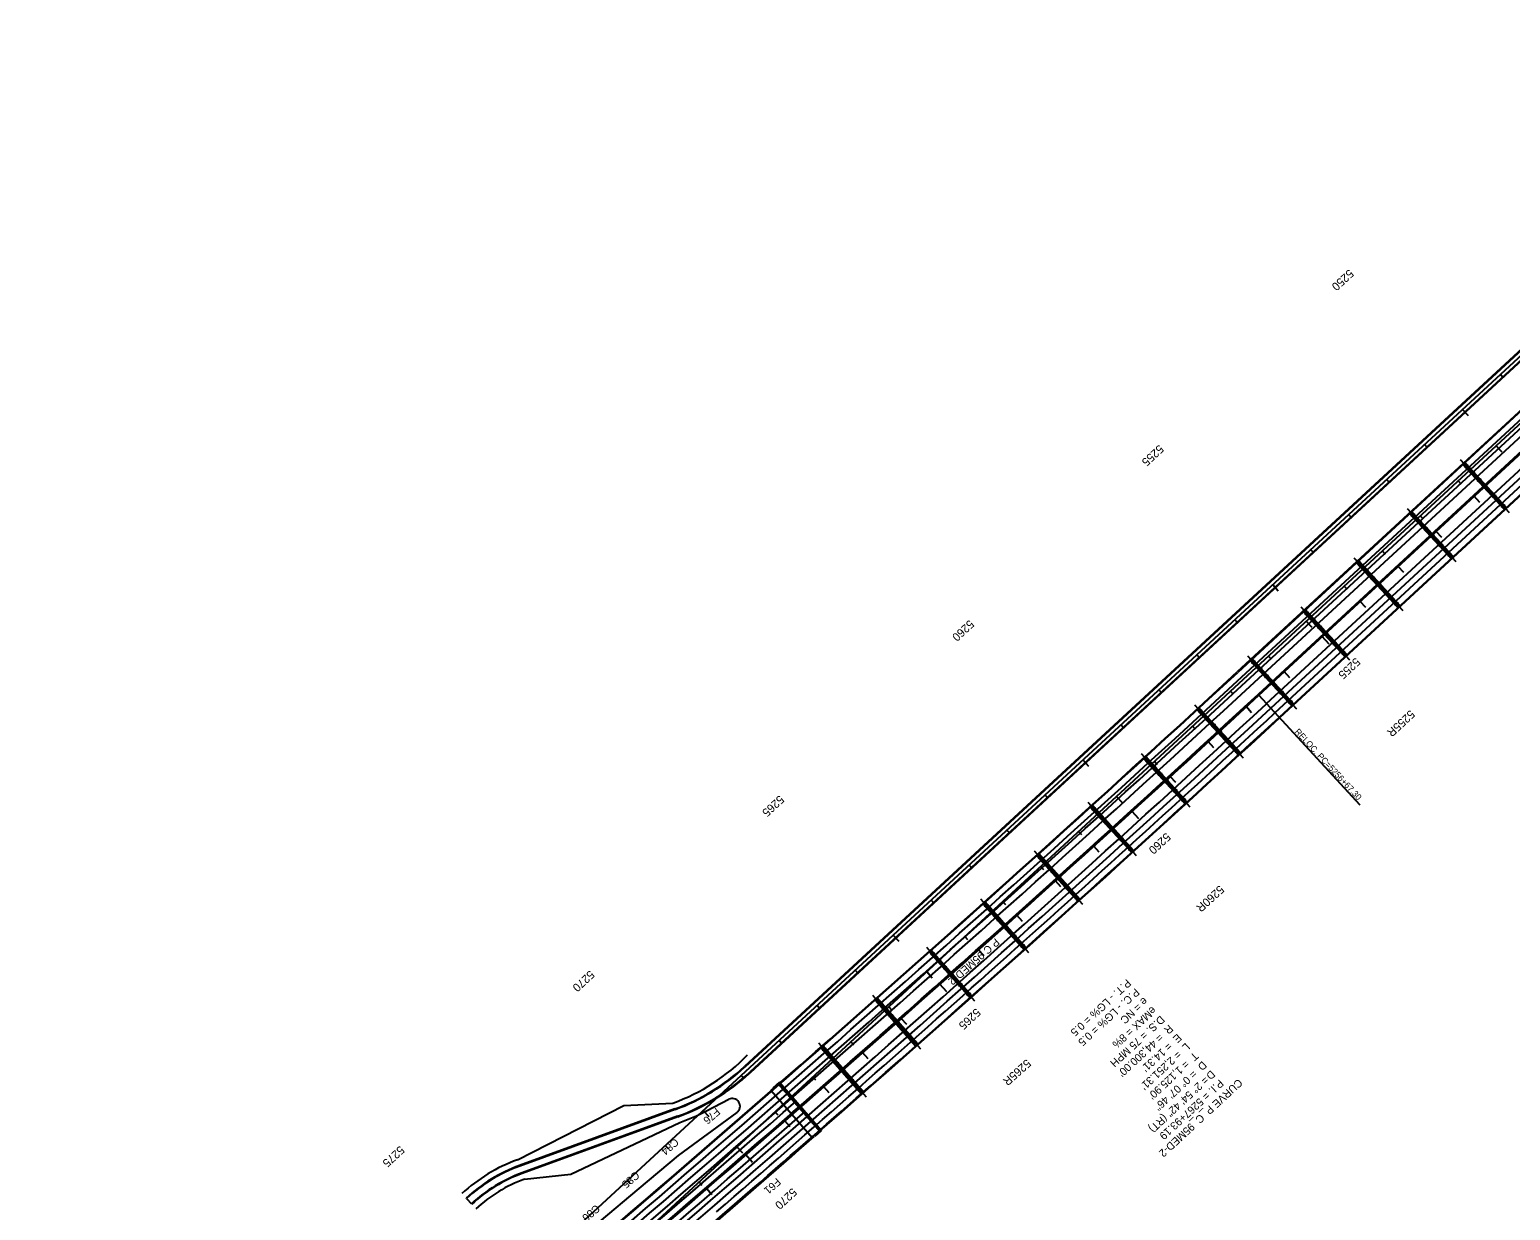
# Model space of a CAD drawing. Extents: x 2160877 to 2175861, y 601747 to 617724.
# Drawn here: x 2163672 to 2166538, y 606904 to 609189 of the extents above; entities that cross this region are included whole.
import ezdxf

# ---------------------------------------------------------------- set-up
doc = ezdxf.new("R2010")
doc.units = 0
for name, color, linetype in [('BR_CENTER LINES', 7, 'Continuous'), ('BR_CONCRETE', 7, 'Continuous'), ('RD_HC_Cl', 7, 'Continuous'), ('RD_HC_CL_Rel', 7, 'Continuous'), ('RD_HC_Data_Rel', 7, 'Continuous'), ('RD_HC_Data_Tic', 7, 'Continuous'), ('RD_HC_Data_Tic_Rel', 7, 'Continuous'), ('RD_HC_TX_Rel_Sta50', 7, 'Continuous'), ('RD_HC_TX_StaOther', 7, 'Continuous'), ('RD_PD_CstnLmt', 7, 'Continuous'), ('RD_PD_CstnLmt_TX', 7, 'Continuous'), ('RD_PD_Final_LnLine', 7, 'Continuous'), ('RD_PD_Final_TrvlWay', 7, 'Continuous'), ('RD_PD_MedBWall', 7, 'Continuous')]:
    doc.layers.add(name, color=color, linetype=linetype)

msp = doc.modelspace()

# ---------------------------------------------------------------- linework, layer by layer
at = {"layer": 'BR_CENTER LINES'}
for p, q in [((2166440.9, 608357.4), (2166535.4, 608255)), ((2166338, 608262.4), (2166432.6, 608160)), ((2166235.2, 608167.4), (2166329.7, 608065.1)), ((2166132.3, 608072.5), (2166226.8, 607970.1)), ((2166029.5, 607977.5), (2166124, 607875.1)), ((2165926.6, 607882.7), (2166020.9, 607780.1)), ((2165823.6, 607788.3), (2165917.5, 607685.4)), ((2165720.2, 607694.2), (2165813.8, 607591)), ((2165616.6, 607600.4), (2165709.9, 607496.9)), ((2165512.6, 607507), (2165605.6, 607403.2)), ((2165408.3, 607413.9), (2165501, 607309.8)), ((2165303.8, 607321.1), (2165396.1, 607216.7)), ((2165199, 607228.6), (2165291, 607124))]:
    msp.add_line(p, q, dxfattribs=at)
at = {"layer": 'BR_CONCRETE'}
for p, q in [((2167286.8, 609125.7), (2166009.5, 607946.3)), ((2167286.8, 609125.6), (2166009.6, 607946.2)), ((2167287.5, 609124.9), (2166010.3, 607945.5)), ((2167326.9, 609082.3), (2166049.6, 607902.9)), ((2167328.4, 609080.5), (2166051.2, 607901.1)), ((2167367.8, 609037.9), (2166090.6, 607858.5)), ((2167368.5, 609037.2), (2166091.2, 607857.8)), ((2167368.6, 609037.1), (2166091.3, 607857.7)), ((2166344.3, 608255.6), (2166426.3, 608166.8)), ((2166241.4, 608160.7), (2166323.5, 608071.8)), ((2165123.7, 607152.2), (2165110.9, 607141)), ((2165122.5, 607149.2), (2165111.9, 607139.9)), ((2165121, 607149.9), (2165202.5, 607056.8)), ((2165122.5, 607149.2), (2165202, 607058.3)), ((2165123.7, 607152.2), (2165205.1, 607059.1)), ((2165107.5, 607136), (2165186.9, 607045.2)), ((2165110.9, 607141), (2165111.9, 607139.9)), ((2165191.3, 607049), (2165202, 607058.3)), ((2165192.3, 607047.9), (2165191.3, 607049)), ((2165192.3, 607047.9), (2165205.1, 607059.1))]:
    msp.add_line(p, q, dxfattribs=at)
for points in [[(2166449.7, 608351.9), (2166445.6, 608348.2), (2166526.6, 608260.5), (2166530.6, 608264.2)], [(2166346.8, 608256.9), (2166342.8, 608253.2), (2166423.8, 608165.5), (2166427.8, 608169.3)], [(2166244, 608161.9), (2166239.9, 608158.2), (2166320.9, 608070.5), (2166324.9, 608074.3)], [(2166141.1, 608067), (2166137.1, 608063.2), (2166218, 607975.6), (2166222.1, 607979.3)], [(2166038.3, 607972), (2166034.2, 607968.3), (2166115.2, 607880.6), (2166119.2, 607884.3)], [(2165935.4, 607877.2), (2165931.4, 607873.5), (2166012.1, 607785.6), (2166016.2, 607789.3)], [(2165832.4, 607782.7), (2165828.3, 607779), (2165908.8, 607690.9), (2165912.8, 607694.6)], [(2165729, 607688.6), (2165724.9, 607684.9), (2165805.1, 607596.6), (2165809.2, 607600.3)], [(2165625.3, 607594.8), (2165621.2, 607591.1), (2165701.1, 607502.5), (2165705.2, 607506.2)], [(2165521.3, 607501.4), (2165517.2, 607497.7), (2165596.9, 607408.8), (2165601, 607412.5)], [(2165417, 607408.2), (2165412.9, 607404.6), (2165492.3, 607315.4), (2165496.4, 607319.1)], [(2165312.5, 607315.4), (2165308.4, 607311.8), (2165387.4, 607222.4), (2165391.6, 607226)], [(2165207.6, 607222.9), (2165203.5, 607219.3), (2165282.3, 607129.7), (2165286.4, 607133.3)]]:
    msp.add_lwpolyline(points, close=True, dxfattribs=at)
for centre, radius in [((2166452.5, 608344.8), 3), ((2166452.5, 608344.8), 2), ((2166464.9, 608331.4), 3), ((2166464.9, 608331.4), 2), ((2166477.4, 608317.9), 3), ((2166477.4, 608317.9), 2), ((2166489.8, 608304.4), 3), ((2166489.8, 608304.4), 2), ((2166506.7, 608286.1), 3), ((2166506.7, 608286.1), 2), ((2166523.7, 608267.7), 3), ((2166523.7, 608267.7), 2), ((2166349.6, 608249.9), 3), ((2166349.6, 608249.9), 2), ((2166362.1, 608236.4), 3), ((2166362.1, 608236.4), 2), ((2166374.5, 608222.9), 3), ((2166374.5, 608222.9), 2), ((2166386.9, 608209.4), 3), ((2166386.9, 608209.4), 2), ((2166403.9, 608191.1), 3), ((2166403.9, 608191.1), 2), ((2166246.8, 608154.9), 3), ((2166246.8, 608154.9), 2), ((2166420.9, 608172.7), 3), ((2166420.9, 608172.7), 2), ((2166259.2, 608141.4), 3), ((2166259.2, 608141.4), 2), ((2166271.6, 608127.9), 3), ((2166271.6, 608127.9), 2), ((2166284.1, 608114.5), 3), ((2166284.1, 608114.5), 2), ((2166301, 608096.1), 3), ((2166301, 608096.1), 2), ((2166318, 608077.7), 3), ((2166318, 608077.7), 2), ((2166143.9, 608059.9), 3), ((2166143.9, 608059.9), 2), ((2166156.3, 608046.4), 3), ((2166156.3, 608046.4), 2), ((2166168.8, 608033), 3), ((2166168.8, 608033), 2), ((2166181.2, 608019.5), 3), ((2166181.2, 608019.5), 2), ((2166198.2, 608001.1), 3), ((2166198.2, 608001.1), 2), ((2166215.1, 607982.8), 3), ((2166215.1, 607982.8), 2), ((2166041.1, 607964.9), 3), ((2166041.1, 607964.9), 2), ((2166053.5, 607951.5), 3), ((2166053.5, 607951.5), 2), ((2166065.9, 607938), 3), ((2166065.9, 607938), 2), ((2166078.4, 607924.5), 3), ((2166078.4, 607924.5), 2), ((2166095.3, 607906.2), 3), ((2166095.3, 607906.2), 2), ((2165938.2, 607870.1), 3), ((2165938.2, 607870.1), 2), ((2166112.3, 607887.8), 3), ((2166112.3, 607887.8), 2), ((2165950.6, 607856.6), 3), ((2165950.6, 607856.6), 2), ((2165963, 607843.1), 3), ((2165963, 607843.1), 2), ((2165975.4, 607829.6), 3), ((2165975.4, 607829.6), 2), ((2165992.3, 607811.2), 3), ((2165992.3, 607811.2), 2), ((2166009.3, 607792.8), 3), ((2166009.3, 607792.8), 2), ((2165835.1, 607775.7), 3), ((2165835.1, 607775.7), 2), ((2165847.5, 607762.1), 3), ((2165847.5, 607762.1), 2), ((2165859.8, 607748.6), 3), ((2165859.8, 607748.6), 2), ((2165872.2, 607735), 3), ((2165872.2, 607735), 2), ((2165889, 607716.6), 3), ((2165889, 607716.6), 2), ((2165905.9, 607698.1), 3), ((2165905.9, 607698.1), 2), ((2165731.7, 607681.5), 3), ((2165731.7, 607681.5), 2), ((2165744, 607668), 3), ((2165744, 607668), 2), ((2165756.3, 607654.4), 3), ((2165756.3, 607654.4), 2), ((2165768.7, 607640.8), 3), ((2165768.7, 607640.8), 2), ((2165785.5, 607622.3), 3), ((2165785.5, 607622.3), 2), ((2165628, 607587.7), 3), ((2165628, 607587.7), 2), ((2165802.3, 607603.8), 3), ((2165802.3, 607603.8), 2), ((2165640.3, 607574.1), 3), ((2165640.3, 607574.1), 2), ((2165652.5, 607560.5), 3), ((2165652.5, 607560.5), 2), ((2165664.8, 607546.9), 3), ((2165664.8, 607546.9), 2), ((2165681.6, 607528.3), 3), ((2165681.6, 607528.3), 2), ((2165524, 607494.2), 3), ((2165524, 607494.2), 2), ((2165698.3, 607509.7), 3), ((2165698.3, 607509.7), 2), ((2165536.2, 607480.6), 3), ((2165536.2, 607480.6), 2), ((2165548.5, 607466.9), 3), ((2165548.5, 607466.9), 2), ((2165560.7, 607453.3), 3), ((2165560.7, 607453.3), 2), ((2165577.4, 607434.7), 3), ((2165577.4, 607434.7), 2), ((2165594.1, 607416), 3), ((2165594.1, 607416), 2), ((2165419.7, 607401.1), 3), ((2165419.7, 607401.1), 2), ((2165431.9, 607387.4), 3), ((2165431.9, 607387.4), 2), ((2165444.1, 607373.7), 3), ((2165444.1, 607373.7), 2), ((2165456.3, 607360), 3), ((2165456.3, 607360), 2), ((2165472.9, 607341.3), 3), ((2165472.9, 607341.3), 2), ((2165489.5, 607322.7), 3), ((2165489.5, 607322.7), 2), ((2165315.1, 607308.3), 3), ((2165315.1, 607308.3), 2), ((2165327.3, 607294.5), 3), ((2165327.3, 607294.5), 2), ((2165339.4, 607280.8), 3), ((2165339.4, 607280.8), 2), ((2165351.6, 607267.1), 3), ((2165351.6, 607267.1), 2), ((2165368.1, 607248.4), 3), ((2165368.1, 607248.4), 2), ((2165210.2, 607215.8), 3), ((2165210.2, 607215.8), 2), ((2165384.7, 607229.6), 3), ((2165384.7, 607229.6), 2), ((2165222.3, 607202), 3), ((2165222.3, 607202), 2), ((2165234.4, 607188.2), 3), ((2165234.4, 607188.2), 2), ((2165246.6, 607174.5), 3), ((2165246.6, 607174.5), 2), ((2165263.1, 607155.7), 3), ((2165263.1, 607155.7), 2), ((2165279.6, 607136.9), 3), ((2165279.6, 607136.9), 2)]:
    msp.add_circle(centre, radius, dxfattribs=at)
for radius, start in [(44239.7, 311.14908), (44239.8, 311.14908), (44240.8, 311.14908), (44298.8, 311.14908), (44301.2, 311.14908), (44300, 312.5847), (44359.2, 311.14908), (44360.2, 311.14908), (44360.3, 311.14908)]:
    msp.add_arc((2135996.9, 640448.5), radius, start, 312.71947, dxfattribs=at)
at = {"layer": 'RD_HC_Cl'}
for p, q in [((2172207.3, 613775.1), (2163672.2, 605893.8)), ((2172272.5, 613704.6), (2163737.4, 605823.3))]:
    msp.add_line(p, q, dxfattribs=at)
at = {"layer": 'RD_HC_CL_Rel'}
msp.add_line((2167327.7, 609081.4), (2166050.4, 607902), dxfattribs=at)
msp.add_arc((2135996.9, 640448.5), 44300, 309.80773, 312.71947, dxfattribs=at)
at = {"layer": 'RD_HC_Data_Rel'}
msp.add_line((2166050.4, 607902), (2166246.8, 607689.4), dxfattribs=at)
at = {"layer": 'RD_HC_Data_Tic'}
for p, q in [((2166518.8, 608522.4), (2166524.2, 608516.5)), ((2166445.3, 608454.5), (2166456.2, 608442.8)), ((2166371.9, 608386.7), (2166377.3, 608380.8)), ((2166510.5, 608384), (2166521.3, 608372.2)), ((2166298.4, 608318.8), (2166303.8, 608313)), ((2166437, 608316.1), (2166442.4, 608310.3)), ((2166224.9, 608251), (2166230.4, 608245.1)), ((2166363.5, 608248.3), (2166369, 608242.4)), ((2166151.5, 608183.1), (2166156.9, 608177.3)), ((2166290.1, 608180.5), (2166295.5, 608174.6)), ((2166078, 608115.3), (2166088.9, 608103.6)), ((2166216.6, 608112.6), (2166222, 608106.7)), ((2166004.5, 608047.5), (2166010, 608041.6)), ((2166143.1, 608044.8), (2166154, 608033)), ((2165931.1, 607979.6), (2165936.5, 607973.7)), ((2166069.7, 607976.9), (2166075.1, 607971.1)), ((2165857.6, 607911.8), (2165863, 607905.9)), ((2165996.2, 607909.1), (2166001.6, 607903.2)), ((2165784.1, 607843.9), (2165789.6, 607838.1)), ((2165922.7, 607841.3), (2165928.2, 607835.4)), ((2165710.7, 607776.1), (2165721.5, 607764.3)), ((2165849.3, 607773.4), (2165854.7, 607767.5)), ((2165637.2, 607708.3), (2165642.6, 607702.4)), ((2165775.8, 607705.6), (2165786.6, 607693.8)), ((2165563.7, 607640.4), (2165569.2, 607634.5)), ((2165702.3, 607637.7), (2165707.7, 607631.9)), ((2165490.3, 607572.6), (2165495.7, 607566.7)), ((2165628.9, 607569.9), (2165634.3, 607564)), ((2165416.8, 607504.7), (2165422.2, 607498.9)), ((2165555.4, 607502.1), (2165560.8, 607496.2)), ((2165343.3, 607436.9), (2165354.2, 607425.1)), ((2165481.9, 607434.2), (2165487.3, 607428.3)), ((2165269.8, 607369.1), (2165275.3, 607363.2)), ((2165408.4, 607366.4), (2165419.3, 607354.6)), ((2165196.4, 607301.2), (2165201.8, 607295.3)), ((2165335, 607298.5), (2165340.4, 607292.7)), ((2165122.9, 607233.4), (2165128.3, 607227.5)), ((2165261.5, 607230.7), (2165266.9, 607224.8)), ((2165049.4, 607165.5), (2165054.9, 607159.7)), ((2165188, 607162.8), (2165193.5, 607157)), ((2164976, 607097.7), (2164986.8, 607085.9)), ((2165114.6, 607095), (2165120, 607089.1)), ((2164902.5, 607029.9), (2164907.9, 607024)), ((2165041.1, 607027.2), (2165052, 607015.4)), ((2164829, 606962), (2164834.5, 606956.1)), ((2164967.6, 606959.3), (2164973.1, 606953.4))]:
    msp.add_line(p, q, dxfattribs=at)
at = {"layer": 'RD_HC_Data_Tic_Rel'}
for p, q in [((2166467.2, 608286.9), (2166478.1, 608275.1)), ((2166393.7, 608219), (2166404.6, 608207.3)), ((2166320.3, 608151.2), (2166331.1, 608139.4)), ((2166246.8, 608083.3), (2166257.7, 608071.6)), ((2166173.3, 608015.5), (2166186.9, 608000.8)), ((2166099.9, 607947.7), (2166110.7, 607935.9)), ((2166026.4, 607879.8), (2166037.2, 607868.1)), ((2165952.8, 607812.1), (2165963.6, 607800.3)), ((2165879, 607744.6), (2165889.8, 607732.8)), ((2165805.1, 607677.2), (2165818.6, 607662.4)), ((2165731.1, 607610), (2165741.8, 607598.2)), ((2165656.9, 607543), (2165667.6, 607531.1)), ((2165582.5, 607476.1), (2165593.2, 607464.2)), ((2165508, 607409.4), (2165518.7, 607397.5)), ((2165433.4, 607342.9), (2165446.7, 607327.9)), ((2165358.6, 607276.5), (2165369.2, 607264.5)), ((2165283.6, 607210.3), (2165294.2, 607198.3)), ((2165208.5, 607144.3), (2165219.1, 607132.3)), ((2165133.3, 607078.4), (2165143.8, 607066.4)), ((2165057.9, 607012.8), (2165071, 606997.7)), ((2164982.3, 606947.2), (2164992.8, 606935.1))]:
    msp.add_line(p, q, dxfattribs=at)
at = {"layer": 'RD_PD_CstnLmt'}
for p, q in [((2164616.2, 607002.2), (2164822.3, 607107.4)), ((2164822.3, 607107.4), (2164917.1, 607111.8)), ((2165041, 607093.8), (2164927.3, 607010.8)), ((2164982, 607096.7), (2165025.2, 607119.2)), ((2164719.7, 606974.6), (2164930.8, 607074.2)), ((2164927.3, 607010.8), (2164851.1, 606946.4)), ((2164629.9, 606964.6), (2164719.7, 606974.6)), ((2165098, 606966.6), (2165022.3, 606901)), ((2164851.1, 606946.4), (2164774.7, 606882.1))]:
    msp.add_line(p, q, dxfattribs=at)
for centre, radius, start, end in [((2164784.3, 607476.4), 388, 290.0109, 315.67), ((2165032.1, 607105.9), 15, 306.1631, 117.5064), ((2164784.3, 607476.4), 428, 290.0109, 297.5064), ((2164725.4, 606702.5), 319, 110.0109, 132.7405), ((2164725.4, 606702.5), 279, 110.0109, 132.7405)]:
    msp.add_arc(centre, radius, start, end, dxfattribs=at)
at = {"layer": 'RD_PD_Final_LnLine'}
for p, q in [((2166018.4, 607936.7), (2167295.7, 609116.1)), ((2166026.6, 607927.8), (2167303.8, 609107.2)), ((2166034.7, 607919), (2167311.9, 609098.4)), ((2166049.6, 607902.9), (2167326.9, 609082.3)), ((2166051.2, 607901.1), (2167328.4, 609080.5)), ((2166066.1, 607885), (2167343.4, 609064.4)), ((2166074.3, 607876.2), (2167351.5, 609055.6)), ((2166082.4, 607867.4), (2167359.7, 609046.8))]:
    msp.add_line(p, q, dxfattribs=at)
for radius, start, end in [(44252.8, 309.80773, 312.71947), (44264.8, 309.80773, 312.71947), (44276.8, 309.80773, 312.71947), (44298.8, 309.80773, 312.71947), (44301.2, 309.80773, 312.71947), (44323.2, 309.80773, 312.71947), (44335.2, 309.80773, 312.71947), (44347.2, 310.84704, 312.71947), (44239.7, 309.80773, 311.15408), (44240.8, 309.80773, 311.15408)]:
    msp.add_arc((2135996.9, 640448.5), radius, start, end, dxfattribs=at)
at = {"layer": 'RD_PD_Final_TrvlWay'}
for centre, radius, start, end in [((2135996.9, 640448.5), 44286.8, 309.80773, 311.17861), ((2135996.9, 640448.5), 44313.2, 309.80773, 311.17861), ((2136000.8, 640444), 44353.2, 310.7522, 311.15415), ((2136000.8, 640444), 44354.3, 310.75222, 311.15415)]:
    msp.add_arc(centre, radius, start, end, dxfattribs=at)
at = {"layer": 'RD_PD_MedBWall'}
for p, q in [((2169697.9, 611469.1), (2165055.7, 607182.5)), ((2169698.6, 611468.4), (2165056.4, 607181.7)), ((2169708.3, 611458.3), (2165065.8, 607171.5)), ((2169684.4, 611434.9), (2165066.5, 607170.7)), ((2164921.2, 607100.5), (2164620.3, 606990.9)), ((2164921.5, 607099.6), (2164620.7, 606990)), ((2164926.3, 607086.4), (2164625.5, 606976.8)), ((2164926.7, 607085.5), (2164625.8, 606975.9)), ((2165190.5, 607047), (2165189.8, 607047.8)), ((2164517.7, 606927.2), (2164517, 606927.9)), ((2164517.7, 606927.2), (2164527.2, 606916.9)), ((2164527.9, 606916.2), (2164527.2, 606916.9))]:
    msp.add_line(p, q, dxfattribs=at)
for centre, radius, start, end in [((2164784.3, 607476.4), 400, 290.0109, 312.7195), ((2164784.3, 607476.4), 401, 290.0109, 312.7195), ((2164784.3, 607476.4), 415, 290.0109, 312.7195), ((2164784.3, 607476.4), 416, 290.0109, 312.7195), ((2136000.8, 640444), 44355.4, 310.75224, 311.15415), ((2164725.4, 606702.5), 307, 110.0109, 132.7405), ((2164725.4, 606702.5), 306, 110.0109, 132.7405), ((2164725.4, 606702.5), 292, 110.0109, 132.7405), ((2164725.4, 606702.5), 291, 110.0109, 132.7405)]:
    msp.add_arc(centre, radius, start, end, dxfattribs=at)

# ---------------------------------------------------------------- texts
at = {"layer": 'RD_HC_Data_Rel'}
for s, height, rotation, p in [('RELOC. PC=5256+67.30', 12, 312.7195, (2166119.7, 607829.9)), ('P C 95MED-2', 15, 221.4251, (2165541.4, 607432)), ('P.T. - LG% = 0.5', 15, 222.7195, (2165795.6, 607352.8)), ('P.C. - LG% = 0.5', 15, 222.7195, (2165811.9, 607335.2)), ('eMAX = 8%', 15, 222.7195, (2165844.4, 607299.9)), ('e = NC', 15, 222.7195, (2165828.1, 607317.6)), ('D.S. = 75 MPH', 15, 222.7195, (2165860.7, 607282.3)), ("R  = 44,300.00'", 15, 222.7195, (2165877, 607264.7)), ("E  = 14.31'", 15, 222.7195, (2165893.3, 607247.1)), ("L  = 2,251.31'", 15, 222.7195, (2165909.6, 607229.4)), ("T  = 1,125.90'", 15, 222.7195, (2165925.8, 607211.8)), ('D  = 0%%d 07\' 46"', 15, 222.7195, (2165942.1, 607194.2)), ('   = 2%%d 54\' 42" (RT)', 15, 222.7195, (2165958.4, 607176.5)), ('CURVE P_C_95MED-2', 15, 222.7195, (2166011.3, 607160)), ('P.I. = 5267+93.19', 15, 222.7195, (2165974.7, 607158.9)), ('D ', 15, 222.7195, (2165958.4, 607176.5))]:
    msp.add_text(s, height=height, rotation=rotation, dxfattribs=at).set_placement(p)
at = {"layer": 'RD_HC_TX_Rel_Sta50'}
for s, rotation, p in [('5255R', 222.7195, (2166344.2, 607873.8)), ('5260R', 222.2892, (2165975.2, 607534.5)), ('5265R', 221.6425, (2165601.6, 607198))]:
    msp.add_text(s, height=16, rotation=rotation, dxfattribs=at).set_placement(p)
at = {"layer": 'RD_HC_TX_StaOther'}
for s, p in [('5250', (2166225.8, 608726.6)), ('5255', (2165858.1, 608387.1)), ('5260', (2165491.2, 608048.2)), ('5255', (2166238.6, 607975.1)), ('5265', (2165123.5, 607708.7)), ('5260', (2165871.6, 607636.2)), ('5270', (2164756.5, 607369.8)), ('5265', (2165503.9, 607296.6)), ('5275', (2164388.8, 607030.3)), ('5270', (2165148.3, 606948.8))]:
    msp.add_text(s, height=16, rotation=222.7195, dxfattribs=at).set_placement(p)
at = {"layer": 'RD_PD_CstnLmt_TX'}
for s, rotation, p in [('F76', 220.9958, (2165000.7, 607103.7)), ('C84', 220.8665, (2164920.6, 607045.2)), ('C85', 220.7371, (2164844.6, 606981)), ('F61', 220.9958, (2165118.1, 606968)), ('C86', 220.6078, (2164768.2, 606916.6))]:
    msp.add_text(s, height=15, rotation=rotation, dxfattribs=at).set_placement(p)

doc.saveas('drawing.dxf')
